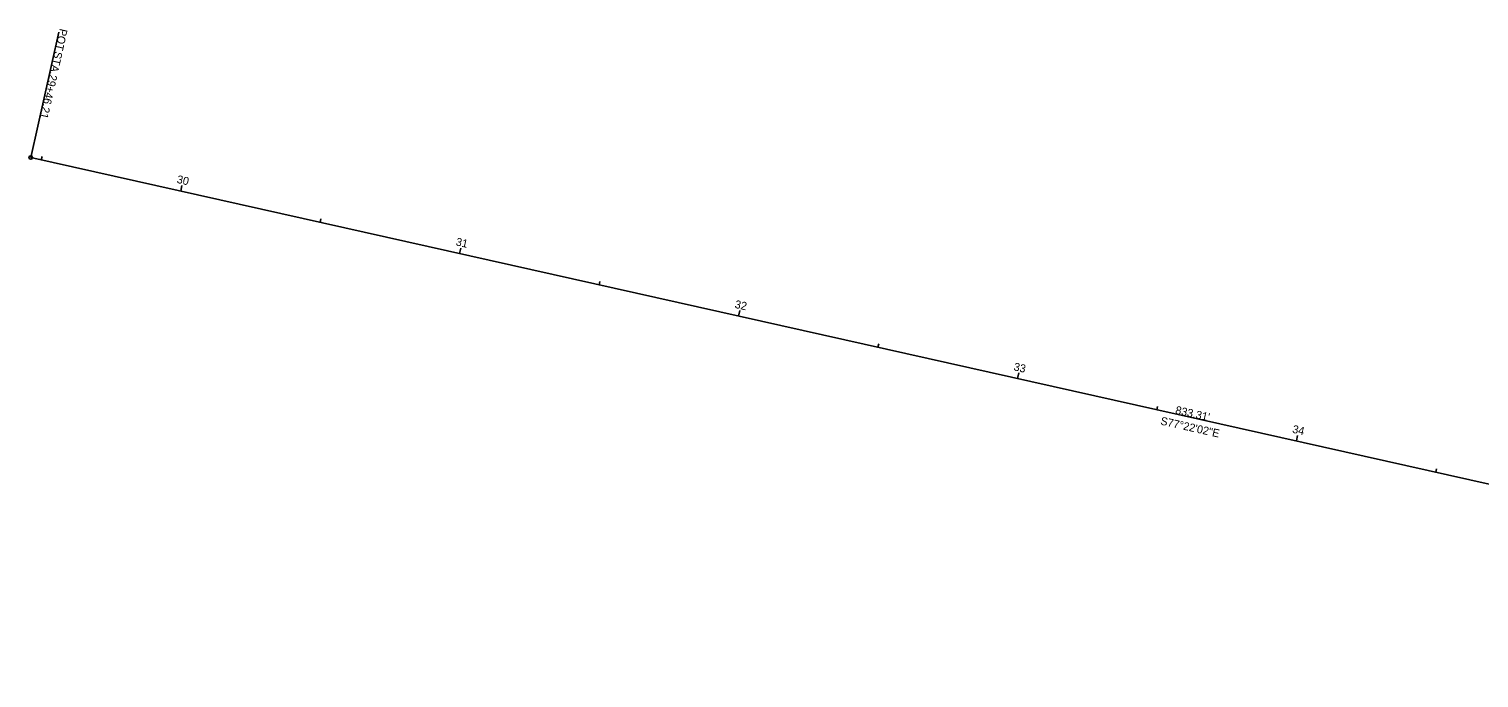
# Model space of a CAD drawing. Extents: x 198556 to 202876, y 391595 to 392065.
# Drawn here: x 198556 to 199063, y 391746 to 391973 of the extents above; entities that cross this region are included whole.
import ezdxf

# ---------------------------------------------------------------- set-up
doc = ezdxf.new("R2010")
doc.units = 0
for name, color, linetype in [('GE_X_Alignment', 7, 'Continuous'), ('GE_X_Alignment_100_Bearings', 7, 'Continuous'), ('GE_X_Alignment_100_Cardinal_Points', 7, 'Continuous'), ('GE_X_Alignment_100_Distances', 7, 'Continuous'), ('GE_X_Alignment_100_Stations', 7, 'Continuous')]:
    doc.layers.add(name, color=color, linetype=linetype)

msp = doc.modelspace()

# ---------------------------------------------------------------- linework, layer by layer
at = {"layer": 'GE_X_Alignment'}
msp.add_line((198556.31, 391927.88), (199369.45, 391745.64), dxfattribs=at)
at = {"layer": 'GE_X_Alignment_100_Cardinal_Points'}
msp.add_line((198556.31, 391927.88), (198566.15, 391971.8), dxfattribs=at)
msp.add_circle((198556.31, 391927.88), 0.6, dxfattribs=at)
at = {"layer": 'GE_X_Alignment_100_Stations'}
for p, q in [((198560.01, 391927.06), (198560.27, 391928.23)), ((198608.8, 391916.12), (198609.24, 391918.07)), ((198657.59, 391905.19), (198657.85, 391906.36)), ((198706.38, 391894.25), (198706.82, 391896.2)), ((198755.17, 391883.32), (198755.43, 391884.49)), ((198803.96, 391872.38), (198804.4, 391874.33)), ((198852.75, 391861.45), (198853.01, 391862.62)), ((198901.54, 391850.51), (198901.97, 391852.46)), ((198950.33, 391839.58), (198950.59, 391840.75)), ((198999.12, 391828.64), (198999.55, 391830.59)), ((199047.91, 391817.71), (199048.17, 391818.88))]:
    msp.add_line(p, q, dxfattribs=at)

# ---------------------------------------------------------------- texts
at = {"layer": 'GE_X_Alignment_100_Bearings'}
msp.add_text('S77°22\'02"E', height=2.8, rotation=347.3672, dxfattribs=at).set_placement((198951.38, 391834.42))
at = {"layer": 'GE_X_Alignment_100_Cardinal_Points'}
for s, p in [('POT', (198566.5, 391973.19)), (' STA. ', (198564.95, 391966.23)), ('29+46.21', (198562.91, 391957.14))]:
    msp.add_text(s, height=2.8, rotation=257.3672, dxfattribs=at).set_placement(p)
at = {"layer": 'GE_X_Alignment_100_Distances'}
msp.add_text("833.31'", height=2.8, rotation=347.3672, dxfattribs=at).set_placement((198956.61, 391838.21))
at = {"layer": 'GE_X_Alignment_100_Stations'}
for s, p in [('30', (198607.25, 391919.03)), ('31', (198704.87, 391897.15)), ('32', (198802.46, 391875.28)), ('33', (198900.05, 391853.4)), ('34', (198997.55, 391831.55))]:
    msp.add_text(s, height=2.8, rotation=347.3672, dxfattribs=at).set_placement(p)

doc.saveas('drawing.dxf')
